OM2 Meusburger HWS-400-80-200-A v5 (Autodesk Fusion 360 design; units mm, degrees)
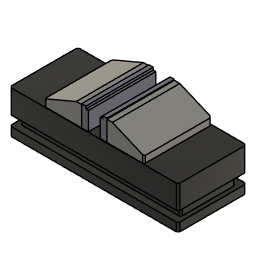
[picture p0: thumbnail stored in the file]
parameter "ouverture" = 20
parameter "d20" = -6
parameter "d21" = 0
parameter "d40" = 0
parameter "d41" = 10
base_feature "Fonction de base1"
base_feature "Fonction de base1"
base_feature "Fonction de base1"
work_plane "Plan de construction1"
position "Position1" TranslateAlongZ 10 (= "ouverture / 2") TranslateAlongZ -10 (= "-ouverture / 2")
position "Position2"
joint_origin "JointOrigin4"
position "Position3" TranslateAlongZ -10 (= "-ouverture / 2") TranslateAlongZ 10 (= "ouverture / 2")
base_feature "Fonction de base1"
position "Position4"
base_feature "Fonction de base1"
position "Position5"
position "Position6"
as_built_joint "Réelle7"
as_built_joint "Réelle8"
work_plane "Plan de construction2"
work_axis "Axe de construction1"
position "Position7"
work_plane "Plan de construction1"
work_plane "Plan de construction1"
work_axis "Axe de construction1"
work_axis "Axe de construction1"
joint "Assembler3" alignAngle 90 alignOffsetX 0 alignOffsetY 0 alignOffsetZ 0
joint "Assembler4" alignAngle 90 alignOffsetX 0 alignOffsetY 0 alignOffsetZ 0
position "Position8" TranslateAlongZ -7 (= "3 mm - ouverture / 2") TranslateAlongZ -7 (= "3 mm - ouverture / 2")
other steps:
step "Fonction de base dérivée"
step "Extrusion1" AlongDistance 7 TaperAngle 0
step "Chanfrein1" Distance 0.25
step "Extrusion5" AlongDistance -2 TaperAngle 0
step "Extrusion6" AlongDistance 7 TaperAngle 0
step "Chanfrein1" Distance 0.25
create_component "CreateComponent3"
create_component "CreateComponent4"
create_component "CreateComponent5"
step "DerivedInstance"
joint "Assembler1" alignAngle 90 alignOffsetX 0 alignOffsetY 0 alignOffsetZ 0
joint "Assembler2" alignAngle 90 alignOffsetX 0 alignOffsetY 0 alignOffsetZ 0
create_component "CreateComponent8"
create_component "CreateComponent9"
joint_origin "JointOrigin9"
joint_origin "JointOrigin11"
joint_origin "JointOrigin14"
joint_origin "JointOrigin13"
